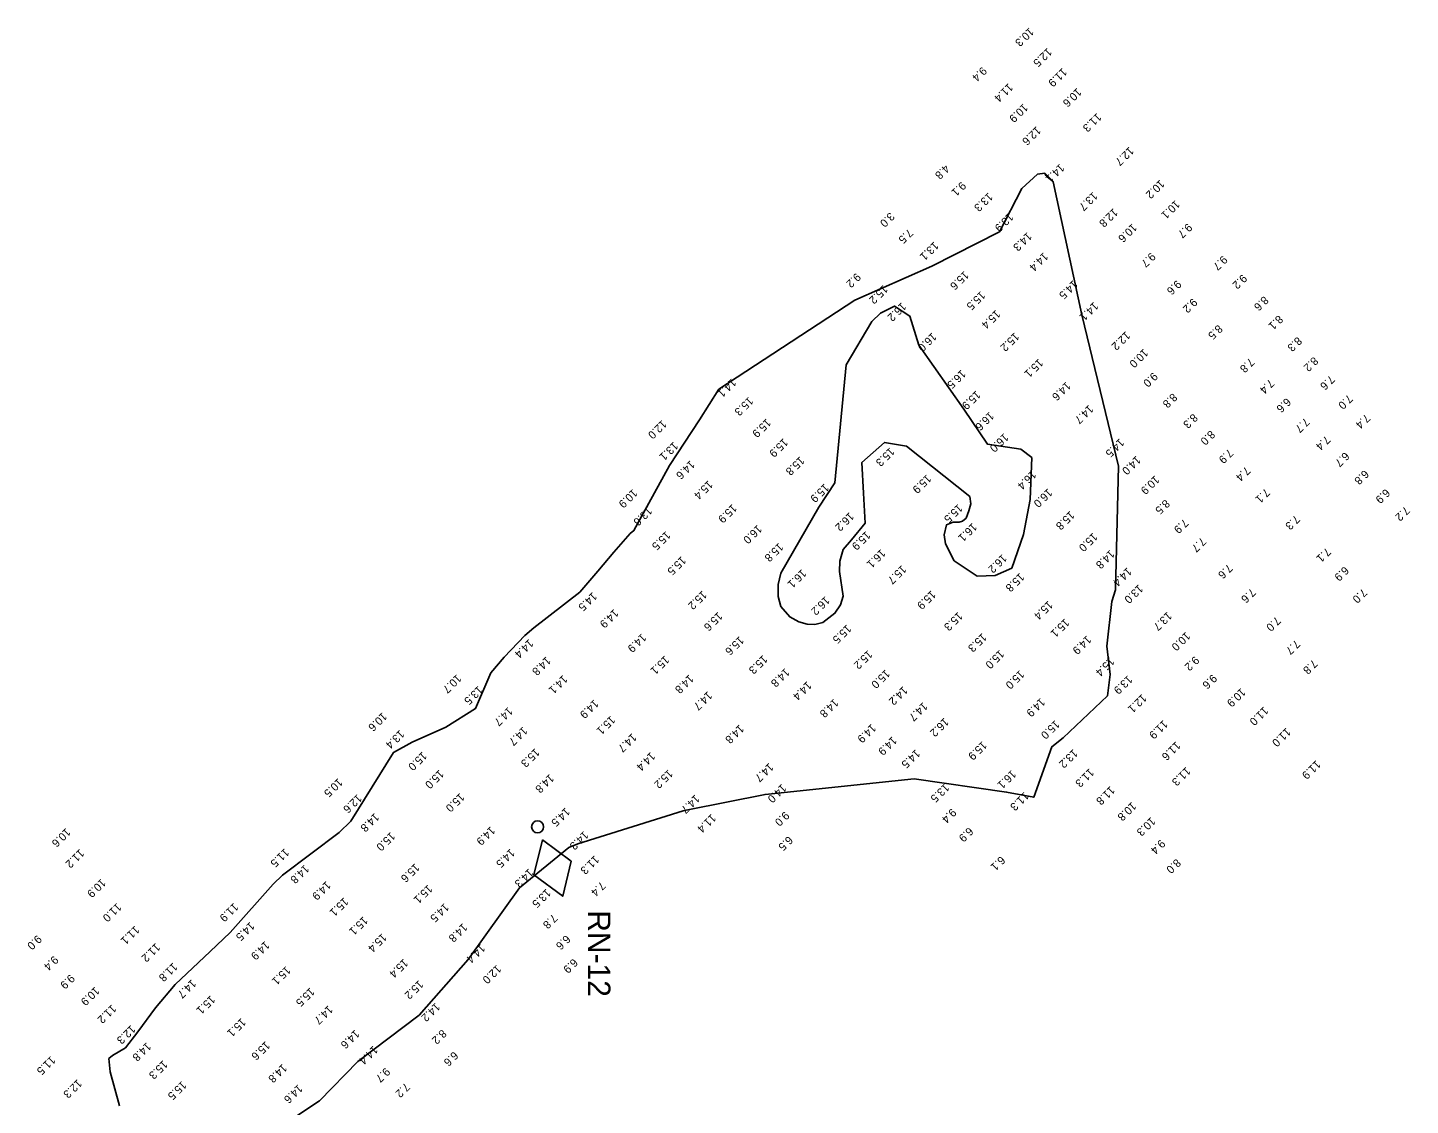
# Model space of a CAD drawing. Extents: x 824616 to 827440, y 158441 to 163197.
# Drawn here: x 825785 to 826649, y 162524 to 163197 of the extents above; entities that cross this region are included whole.
import ezdxf

# ---------------------------------------------------------------- set-up
doc = ezdxf.new("R2010")
doc.units = 0
for name, color, linetype in [('V-CHAN-CONT-EL14', 7, 'Continuous'), ('V-CHAN-CONT-EL16', 7, 'Continuous'), ('V-CHAN-NAID', 7, 'Continuous'), ('V-TOPO-SOUN', 7, 'Continuous')]:
    doc.layers.add(name, color=color, linetype=linetype)

msp = doc.modelspace()

# ---------------------------------------------------------------- linework, layer by layer
at = {"layer": 'V-CHAN-CONT-EL14'}
msp.add_lwpolyline([(825952.94, 162517.67), (825967.03, 162527.15), (825991.1, 162551.8), (826029.35, 162580.64), (826060.06, 162615.45), (826092.14, 162660.16), (826122.86, 162685.42), (826128.54, 162687.59), (826194.44, 162708.36), (826197.23, 162708.81), (826245.59, 162718.54), (826338.75, 162728.34), (826396.46, 162719.95), (826413.49, 162716.71), (826424.72, 162748.34), (826431.81, 162753.82), (826459.45, 162780.13), (826461.16, 162793.35), (826459.07, 162811.21), (826462.17, 162839.08), (826464.51, 162846.38), (826466.5, 162923.47), (826443.4, 163017.99), (826425.63, 163101.25), (826420.41, 163106.55), (826415.84, 163105.95), (826405.98, 163096.98), (826392.11, 163070.03), (826349.75, 163048.51), (826301.71, 163027.15), (826216.66, 162971.65), (826204.56, 162952.44), (826185.8, 162923.88), (826163.54, 162883.29), (826161.32, 162881.41), (826151.09, 162869.89), (826141.12, 162857.91), (826129.75, 162844.92), (826101.07, 162822.55), (826095.31, 162817.77), (826082.48, 162804.18), (826074.18, 162794.5), (826064.61, 162772.16), (826046.13, 162760.54), (826025.02, 162751.09), (826013.39, 162744.72), (825986.65, 162701.86), (825979.47, 162694.78), (825944.01, 162668.03), (825938.09, 162662.46), (825911.22, 162632.36), (825898.81, 162620.47), (825876.96, 162599.85), (825864.51, 162585.13), (825853.49, 162570.15), (825845.82, 162560.23), (825837.74, 162555.42), (825835.44, 162553.55), (825836.26, 162545.19), (825842.02, 162524.1)], dxfattribs=at)
msp.add_lwpolyline([(826421.06, 163105.9), (826421.15, 163105.81), (826421.25, 163105.72), (826425.1, 163101.84), (826425.51, 163101.41), (826425.63, 163101.25), (826425.45, 163101.35), (826424.99, 163101.71), (826421.76, 163104.31), (826421.55, 163104.49), (826421.37, 163104.69), (826421.21, 163104.91), (826421.08, 163105.15), (826420.45, 163106.42), (826420.41, 163106.51), (826420.41, 163106.55), (826420.45, 163106.53), (826420.52, 163106.47), (826420.88, 163106.09), (826420.97, 163106)], close=True, dxfattribs=at)
at = {"layer": 'V-CHAN-CONT-EL16'}
msp.add_lwpolyline([(826312.34, 163014.02), (826296.23, 162986.93), (826289.09, 162913.18), (826279.1, 162897.96), (826255.32, 162856.77), (826253.75, 162849.6), (826253.79, 162842.07), (826255.38, 162835.91), (826260.96, 162829.43), (826266.64, 162826.24), (826271.77, 162824.97), (826276.66, 162824.67), (826281.54, 162825.87), (826289.2, 162831.64), (826292.65, 162836.87), (826294.35, 162842.37), (826292.15, 162857.7), (826292.35, 162864.12), (826294.4, 162871.58), (826299.48, 162877.61), (826308.11, 162887.86), (826307.02, 162906.8), (826305.92, 162925.75), (826320.08, 162938.38), (826333.97, 162936.04), (826373.6, 162904.53), (826374.21, 162900.05), (826372.87, 162895.57), (826371.24, 162891.14), (826368.95, 162889.14), (826366.78, 162888.61), (826363.07, 162888.57), (826358.98, 162886.98), (826357.49, 162880.77), (826358.23, 162875.15), (826363.68, 162864.45), (826378.14, 162854.82), (826389.4, 162855.34), (826399.72, 162859.86), (826407.05, 162880.81), (826411.24, 162902.82), (826412.25, 162928.9), (826405.43, 162934.09), (826384.45, 162937.31), (826369.7, 162959.22), (826341.53, 162999.14), (826336.1, 163017.29), (826326.45, 163023.6), (826317.64, 163019.09)], close=True, dxfattribs=at)
at = {"layer": 'V-CHAN-NAID'}
msp.add_lwpolyline([(826106.35, 162690.08), (826101.04, 162668.24), (826119.15, 162654.93), (826124.47, 162676.77)], close=True, dxfattribs=at)
msp.add_circle((826103.37, 162698.28), 3.74, dxfattribs=at)

# ---------------------------------------------------------------- texts
msp.add_text('RN-12', height=14, rotation=270, dxfattribs=at).set_placement((826134.89, 162646.17))
at = {"layer": 'V-TOPO-SOUN'}
for s, p in [('10.3 ', (826410.67, 163197.82)), ('12.5 ', (826421.97, 163185.12)), ('9.4', (826381.23, 163173.36)), ('11.9 ', (826431.37, 163172.61)), ('11.4 ', (826397.67, 163163.09)), ('10.6 ', (826440.49, 163160.07)), ('10.9 ', (826406.96, 163150.37)), ('11.3 ', (826452.95, 163144.45)), ('12.6 ', (826415.1, 163136.14)), ('12.7 ', (826473.19, 163123.4)), ('4.8', (826357.95, 163112.33)), ('14.1 ', (826429.75, 163112.77)), ('9.1', (826368.25, 163101.62)), ('10.2 ', (826492.36, 163102.78)), ('13.3 ', (826385.05, 163094.72)), ('13.7 ', (826450.53, 163095.24)), ('12.8 ', (826463.18, 163084.94)), ('10.1 ', (826501.97, 163090.04)), ('3.0', (826323.57, 163082.39)), ('13.9 ', (826397.92, 163082.07)), ('10.6 ', (826475.1, 163075.47)), ('9.7', (826509.6, 163075.56)), ('7.5', (826335.13, 163072.15)), ('14.3 ', (826409.43, 163069.99)), ('13.1 ', (826351.16, 163064.12)), ('14.4 ', (826419.6, 163057.43)), ('9.7', (826486.68, 163057.36)), ('9.7', (826531.62, 163055.43)), ('9.2', (826302.5, 163044.57)), ('15.6 ', (826370.04, 163045.78)), ('9.2', (826543.85, 163043.76)), ('15.2 ', (826319.47, 163037)), ('15.5 ', (826380.32, 163033.18)), ('14.5 ', (826438.11, 163040)), ('9.6', (826502.83, 163040.12)), ('16.2 ', (826330.94, 163026.16)), ('14.1 ', (826450.98, 163026.43)), ('9.2', (826512.79, 163028.82)), ('8.6', (826557.27, 163030.12)), ('15.4 ', (826389.74, 163021.45)), ('8.1', (826566.35, 163018.2)), ('16.0 ', (826349.89, 163007.27)), ('15.2 ', (826401.51, 163007.34)), ('12.2 ', (826470.94, 163008.07)), ('8.5', (826528.58, 163012.24)), ('10.0 ', (826482.12, 162997.19)), ('8.3', (826578.18, 163004.68)), ('15.1 ', (826416.5, 162990.95)), ('7.8', (826548.48, 162991.47)), ('8.2', (826588.33, 162992.18)), ('16.5 ', (826368.19, 162984.09)), ('9.0', (826488.05, 162982.52)), ('7.6', (826598.62, 162980.67)), ('14.1 ', (826224.68, 162978.6)), ('14.6 ', (826433.72, 162976.62)), ('7.4', (826560.88, 162978.25)), ('15.3 ', (826235.35, 162967.17)), ('15.9 ', (826377.4, 162971.03)), ('8.8', (826500.24, 162969.48)), ('6.6', (826571.33, 162966.55)), ('7.0', (826609.93, 162968.61)), ('16.6 ', (826385.79, 162957.86)), ('14.7 ', (826447.89, 162962.14)), ('8.3', (826513.03, 162956.72)), ('7.4', (826620.81, 162956.48)), ('12.0 ', (826181.25, 162952.69)), ('15.9 ', (826246.41, 162953.58)), ('8.0', (826523.86, 162946.23)), ('7.7', (826582.96, 162954.06)), ('13.1 ', (826188.39, 162939.08)), ('15.9 ', (826257.04, 162941.25)), ('16.0 ', (826394.84, 162944.41)), ('14.5 ', (826467.18, 162941.19)), ('7.4', (826595.9, 162942.99)), ('15.8 ', (826267.32, 162929.91)), ('15.3 ', (826323.62, 162935.51)), ('14.0 ', (826477.51, 162930.31)), ('7.9', (826535.26, 162934.72)), ('6.7', (826607.84, 162932.71)), ('14.6 ', (826198.8, 162927.49)), ('16.4 ', (826412.16, 162921.12)), ('7.4', (826545.95, 162923.67)), ('6.8', (826620.01, 162921.54)), ('15.4 ', (826210.07, 162914.94)), ('15.9 ', (826282.67, 162912.98)), ('15.9 ', (826346.56, 162918.64)), ('10.9 ', (826489.14, 162918.03)), ('10.9 ', (826162.92, 162909.59)), ('16.0 ', (826422.25, 162909.92)), ('8.5', (826495.59, 162903.06)), ('7.1', (826558.17, 162909.98)), ('6.9', (826633.23, 162909.76)), ('13.6 ', (826172.18, 162898.47)), ('15.9 ', (826225.09, 162900.17)), ('16.2 ', (826298.28, 162895.06)), ('15.5 ', (826366.2, 162900.19)), ('15.8 ', (826436.14, 162895.85)), ('7.2', (826645.54, 162898.79)), ('16.0 ', (826240.78, 162887.2)), ('16.1 ', (826375.13, 162888.41)), ('7.9', (826507.23, 162891.01)), ('7.3', (826576.89, 162893.32)), ('15.5 ', (826183.65, 162883.26)), ('15.9 ', (826308.6, 162883.24)), ('15.0 ', (826450.47, 162882.29)), ('7.7', (826518.25, 162879.42)), ('15.5 ', (826193.34, 162867.57)), ('15.8 ', (826254.12, 162875.96)), ('16.1 ', (826318.01, 162872.03)), ('16.2 ', (826393.84, 162868.9)), ('14.8 ', (826461.12, 162871.57)), ('7.1', (826596.29, 162872.98)), ('16.1 ', (826268.5, 162859.47)), ('15.7 ', (826330.97, 162862.01)), ('14.4 ', (826471.85, 162860.6)), ('7.6', (826534.84, 162862.75)), ('6.9', (826607.52, 162861.31)), ('15.8 ', (826404.74, 162857.19)), ('14.5 ', (826137.71, 162845.16)), ('15.2 ', (826206.34, 162846.1)), ('16.2 ', (826283.17, 162842.6)), ('15.9 ', (826349.39, 162846.23)), ('13.0 ', (826478.95, 162849.93)), ('7.6', (826549.25, 162847.61)), ('7.0', (826618.86, 162847.51)), ('14.9 ', (826151.11, 162834.6)), ('15.4 ', (826422.52, 162839.77)), ('13.7 ', (826497, 162832.94)), ('15.6 ', (826216.16, 162832.75)), ('15.5 ', (826296.63, 162824.89)), ('15.3 ', (826366.24, 162832.8)), ('15.1 ', (826432.87, 162828.7)), ('7.0', (826564.9, 162829.95)), ('14.4 ', (826097.98, 162815.77)), ('14.9 ', (826168.49, 162819.34)), ('15.6 ', (826229.5, 162817.63)), ('15.3 ', (826381.23, 162819.55)), ('14.9 ', (826446.58, 162818.08)), ('10.0 ', (826508.44, 162820.34)), ('15.2 ', (826309.85, 162808.89)), ('15.0 ', (826392.14, 162809.11)), ('7.7', (826577.05, 162815.38)), ('14.8 ', (826108.83, 162804.95)), ('15.1 ', (826182.87, 162805.47)), ('15.3 ', (826244.23, 162805.8)), ('15.4 ', (826461.01, 162804.43)), ('9.2', (826513.97, 162805.25)), ('7.8', (826587.93, 162803.13)), ('10.7 ', (826052.96, 162793.85)), ('14.1 ', (826119.28, 162793.33)), ('14.8 ', (826198.12, 162793.65)), ('14.8 ', (826258.05, 162797.67)), ('15.0 ', (826320.77, 162796.84)), ('15.0 ', (826404.72, 162796.45)), ('13.9 ', (826472.3, 162793.23)), ('9.6', (826525.06, 162793.92)), ('13.5 ', (826066.37, 162786.65)), ('14.7 ', (826209.72, 162783.18)), ('14.4 ', (826271.83, 162789.45)), ('14.2 ', (826331.79, 162786.38)), ('12.1 ', (826481.18, 162781.53)), ('10.9 ', (826543.03, 162785.25)), ('14.7 ', (826085.04, 162773.42)), ('14.9 ', (826138.66, 162778.07)), ('14.8 ', (826288.57, 162778.63)), ('14.7 ', (826344.25, 162776.39)), ('14.9 ', (826417.73, 162779.09)), ('11.0 ', (826557.2, 162773.67)), ('10.6 ', (826006.45, 162770.07)), ('15.1 ', (826149.12, 162767.96)), ('16.2 ', (826357.53, 162766.65)), ('15.0 ', (826426.79, 162765.2)), ('11.9 ', (826494.39, 162765.27)), ('13.4 ', (826017.31, 162759.12)), ('14.7 ', (826094.2, 162761.11)), ('14.7 ', (826162.44, 162756.99)), ('14.8 ', (826229.54, 162762.39)), ('14.9 ', (826312.08, 162762.85)), ('11.0 ', (826571.24, 162760.42)), ('15.3 ', (826101.86, 162747.6)), ('14.9 ', (826325.08, 162755.07)), ('14.5 ', (826339.63, 162746.98)), ('15.9 ', (826381.34, 162752.08)), ('13.2 ', (826438.12, 162747.1)), ('11.6 ', (826502.33, 162751.88)), ('15.0 ', (826031.4, 162745.51)), ('14.4 ', (826174.1, 162745.27)), ('14.7 ', (826248.01, 162738.45)), ('11.9 ', (826589.92, 162740.13)), ('15.0 ', (826041.97, 162734.18)), ('14.8 ', (826110.84, 162731.51)), ('15.2 ', (826185.11, 162734.37)), ('16.1 ', (826399.59, 162734.07)), ('11.3 ', (826448.3, 162735.13)), ('11.3 ', (826508.63, 162735.97)), ('10.5 ', (825978.76, 162728.94)), ('14.0 ', (826256.02, 162725.39)), ('13.5 ', (826357.81, 162725.64)), ('11.8 ', (826461.32, 162724.04)), ('12.6 ', (825990.79, 162718.99)), ('15.0 ', (826054.86, 162719.66)), ('14.7 ', (826201.86, 162718.7)), ('11.3 ', (826407.58, 162720.43)), ('10.8 ', (826474.68, 162714.09)), ('14.8 ', (826001.57, 162707.22)), ('14.5 ', (826120.8, 162710.59)), ('11.4 ', (826212.08, 162706.67)), ('9.0', (826257.85, 162708.22)), ('9.4', (826362.19, 162710.11)), ('10.3 ', (826486.64, 162704.64)), ('10.6 ', (825808.68, 162697.76)), ('15.0 ', (826011.53, 162695.32)), ('14.9 ', (826074.04, 162698.87)), ('14.3 ', (826132.32, 162695.95)), ('6.9', (826372.81, 162698.36)), ('6.5', (826260.05, 162692.86)), ('9.4', (826492.74, 162690.69)), ('11.2 ', (825817.27, 162684.7)), ('11.5 ', (825945.32, 162685.16)), ('14.5 ', (826086.31, 162684.91)), ('11.3 ', (826139.05, 162680.72)), ('6.1', (826392.76, 162680.33)), ('8.0', (826502.5, 162678.67)), ('14.8 ', (825957.78, 162674.95)), ('15.6 ', (826026.8, 162675.74)), ('14.3 ', (826097.91, 162672.51)), ('10.9 ', (825830.73, 162666.22)), ('14.9 ', (825971.35, 162664.65)), ('15.1 ', (826034.84, 162662.41)), ('7.4', (826142.99, 162664.43)), ('15.1 ', (825982.33, 162654.44)), ('13.5 ', (826108.83, 162659.87)), ('11.0 ', (825840.53, 162651.03)), ('11.9 ', (825913.56, 162651.1)), ('14.5 ', (826045.15, 162650.88)), ('7.8', (826112.92, 162644.13)), ('11.1 ', (825851.75, 162636.8)), ('14.5 ', (825923.7, 162639.18)), ('15.1 ', (825994.49, 162642.63)), ('14.8 ', (826056.68, 162638.34)), ('9.0', (825790.66, 162631.02)), ('11.2 ', (825864.77, 162625.97)), ('14.9 ', (825933.12, 162627.23)), ('15.4 ', (826006.29, 162632.06)), ('6.6', (826121.04, 162631.03)), ('9.4', (825801.07, 162618.07)), ('14.4 ', (826067.78, 162625.34)), ('11.8 ', (825875.56, 162613.73)), ('15.1 ', (825946.2, 162611.54)), ('15.4 ', (826019.64, 162616.13)), ('12.0 ', (826077.85, 162612.38)), ('6.9', (826125.64, 162616.35)), ('9.9', (825811.28, 162606.49)), ('14.7 ', (825887.21, 162603.31)), ('15.2 ', (826029.18, 162602.74)), ('10.9 ', (825826.79, 162598.72)), ('15.1 ', (825899.08, 162593.26)), ('15.5 ', (825961.2, 162598.14)), ('11.2 ', (825837.28, 162587.56)), ('14.7 ', (825972.65, 162587.04)), ('14.2 ', (826039.61, 162588.73)), ('12.3 ', (825849.3, 162574.71)), ('15.1 ', (825918.29, 162579.12)), ('14.6 ', (825989.22, 162571.82)), ('8.2', (826043.59, 162572.02)), ('14.8 ', (825859.06, 162563.97)), ('15.6 ', (825933.38, 162564.68)), ('14.4 ', (826000.76, 162561.85)), ('6.6', (826050.94, 162558.33)), ('11.5 ', (825799.26, 162555.44)), ('15.3 ', (825869.39, 162552.75)), ('14.8 ', (825943.98, 162550.54)), ('9.7', (826008.35, 162548.2)), ('12.3 ', (825815.88, 162540.92)), ('15.5 ', (825881.14, 162539.83)), ('14.6 ', (825953.75, 162537.68)), ('7.2', (826020.74, 162538.68))]:
    msp.add_text(s, height=5, rotation=224.2, dxfattribs=at).set_placement(p)

doc.saveas('drawing.dxf')
